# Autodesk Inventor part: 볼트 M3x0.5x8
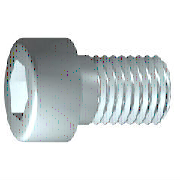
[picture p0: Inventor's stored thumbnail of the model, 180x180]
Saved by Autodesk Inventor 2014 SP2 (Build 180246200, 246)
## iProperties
IsCustomPart: 1
Company: 한국ATC센터
Created: 2015-12
Part Number: 볼트 M3x0.5x8
Material: 스테인리스강
Description: 6각머리 태핑 나사
Document SubType Name: Modeling
Standard: KS B 1003
Designer: mdu
Standards Organization: KS
Language: ko-KR
Size Designation: M 4 x 12
Categories: <MemberInstance><Categories><Category DisplayName="조임쇠" InternalName="e4da775c-781d-43d5-af7c-5136215cf5a6" Mnemonic="FSTN"><Category DisplayName="볼트" InternalN
Density: 8.08 g/cm^3
Mass: 1.41278 g
Surface Area: 2.584 cm^2
Volume: 0.174849 cm^3
Appearance: 반광택
Author: mdu
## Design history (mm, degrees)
sketch "스케치1"
  geometry: L1 (-0.867, 0)-(16, 0); L2 (16, 0)-(16, 1.5); L3 (16, 1.5)-(1.25, 1.5); L4 (1.25, 1.5)-(0.943, 1.5); L5 (0.943, 1.5)-(0, 1.5); L6 (0, 1.5)-(0, 2.75); L7 (0, 2.75)-(-3, 2.75); L8 (-3, 2.75)-(-3, 1.443); L9 (-3, 1.443)-(-1.7, 1.443); L10 (-1.7, 1.443)-(-0.867, 0); L11 (-6.8, 0)-(19.8, 0) reference; L12 (0, -0.55)-(0, 3.3) reference; L13 (1.25, 1.5)-(0, 1.5)
  constraints: 22 end point, 6 parallel, 2 collinear, 2 perpendicular, 1 horizontal, 1 point on line
  dimensions: "d1" = 14.75 distance from line of L3.end L2 (= GEL); "d2" = 0.30683 distance of L4.end L3.end (computed from GAL); "d3" = 3 distance between parallel lines of L8 L6 (= KOH); "d4" = 1.3 distance of L8.end L9.end (= INTI); "d5" = 60 deg angle of L10 L1; "d6" = 3 diameter of L3 L1 (= GD); "d7" = 3 diameter of L5 L1 (= BDM); "d8" = 2.88675 diameter of L9 L1 (= 1.1547 x SW); "d9" = 5.5 diameter of L7 L1 (= KOD); "d26" = 16 distance between parallel lines of L12 L2 (= NLG)
revolve "본체" sketch "스케치1" stored, may be unused: angle "d10" = 90 deg
sketch "스케치2"
  geometry: L1 (0, -3.85)-(0, 3.85) reference; L2 (-3.85, 0)-(3.85, 0) reference; L3 (1.443, 0)-(0.722, -1.25); L4 (0.722, -1.25)-(-0.722, -1.25); L5 (-0.722, -1.25)-(-1.443, 0); L6 (-1.443, 0)-(-0.722, 1.25); L7 (-0.722, 1.25)-(0.722, 1.25); L8 (0.722, 1.25)-(1.443, 0); 2 further points
  constraints: 12 end point, 1 coincident, 1 horizontal alignment, 1 point on line, 12 other
extrude "슬롯" join sketch "스케치2" stored distance "d11" = 10; taper "d12" = 0 deg
workplane "Work Plane1"
fillet "Fillet2" dims "d30" = 0.1 (= R)
body "Solid1"
fillet "모깎기1" dims "d17" = 0.3 (= RR)
feature "스레드" dims "d13" = 14.75 (= GEL), "d14" = 0
chamfer "모따기1" distance "d15" = 0.30673 (= -0.5 x SPD + 0.5 x GD); stored, may be unused: second distance "d16" = 0.30673 (= GUL), angle "d27" = 45 deg
other parameters: "GD" = 3 (= NND) [user parameter; used in 2 equation terms], "NLG" = 16 [user parameter; used in 1 equation term], "GEL" = 14.75 [user parameter; used in 2 equation terms], "KOD" = 5.5 [user parameter; used in 1 equation term], "KOH" = 3 [user parameter; used in 1 equation term], "INTI" = 1.3 [user parameter; used in 1 equation term], "GAL" = 0.30673 (= 0.61345 x PTC) [user parameter; used in 1 equation term], "GUL" = 0.30673 (= 0.61345 x PTC) [user parameter; used in 1 equation term], "BDM" = 3 (= NND) [user parameter; used in 1 equation term], "SW" = 2.5 [user parameter; used in 2 equation terms], "RR" = 0.3 [user parameter; used in 1 equation term], "SPD" = 2.38655 (= NND - 1.2269 x PTC) [user parameter; used in 1 equation term], "d19" = 0, "d28" = 0, "d29" = 0, "R" = 0.1 [user parameter; used in 1 equation term], "PHH" = 0.1 [user parameter], "GD1" = 2.38655 (= THREADDIA - 1.2269 x PTC) [user parameter], "THREADDIA" = 3 [user parameter; used in 1 equation term], "FAWI" = 45 deg [user parameter], "PTC" = 0.5 [user parameter; used in 5 equation terms], "NND" = 3 [user parameter; used in 3 equation terms], "TOA" = 30 deg [user parameter], "E0" = 2.8875 (= 1.155 x SW) [user parameter]
